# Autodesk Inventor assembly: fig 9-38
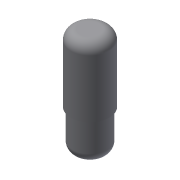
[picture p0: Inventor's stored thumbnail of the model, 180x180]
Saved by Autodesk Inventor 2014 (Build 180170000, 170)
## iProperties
Created: 2013-07
Part Number: fig 9-38
Document SubType Name: Assembly
Designer: CADCIM
Author: CADCIM
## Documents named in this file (3)
- E:\APS\Autodesk Inventor 2014-Project\inventor_2014_partfiles\Inventor_2014_prt\c09_Inv_2014_prt\c09_inv_2014_prt\fig 9-38.iam
- E:\APS\Autodesk Inventor 2014-Project\inventor_2014_partfiles\Inventor_2014_prt\c09_Inv_2014_prt\c09_inv_2014_prt\10.ipt
- E:\APS\Autodesk Inventor 2014-Project\inventor_2014_partfiles\Inventor_2014_prt\c09_Inv_2014_prt\c09_inv_2014_prt\11.ipt
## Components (2 placed, 2 different names)
1. 10:1 — Rigid:1
2. 11:1 — Rigid:1
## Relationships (1: WeldJoint 1)
- Rigid:1 [WeldJoint]: 10:1 ↔ 11:1
